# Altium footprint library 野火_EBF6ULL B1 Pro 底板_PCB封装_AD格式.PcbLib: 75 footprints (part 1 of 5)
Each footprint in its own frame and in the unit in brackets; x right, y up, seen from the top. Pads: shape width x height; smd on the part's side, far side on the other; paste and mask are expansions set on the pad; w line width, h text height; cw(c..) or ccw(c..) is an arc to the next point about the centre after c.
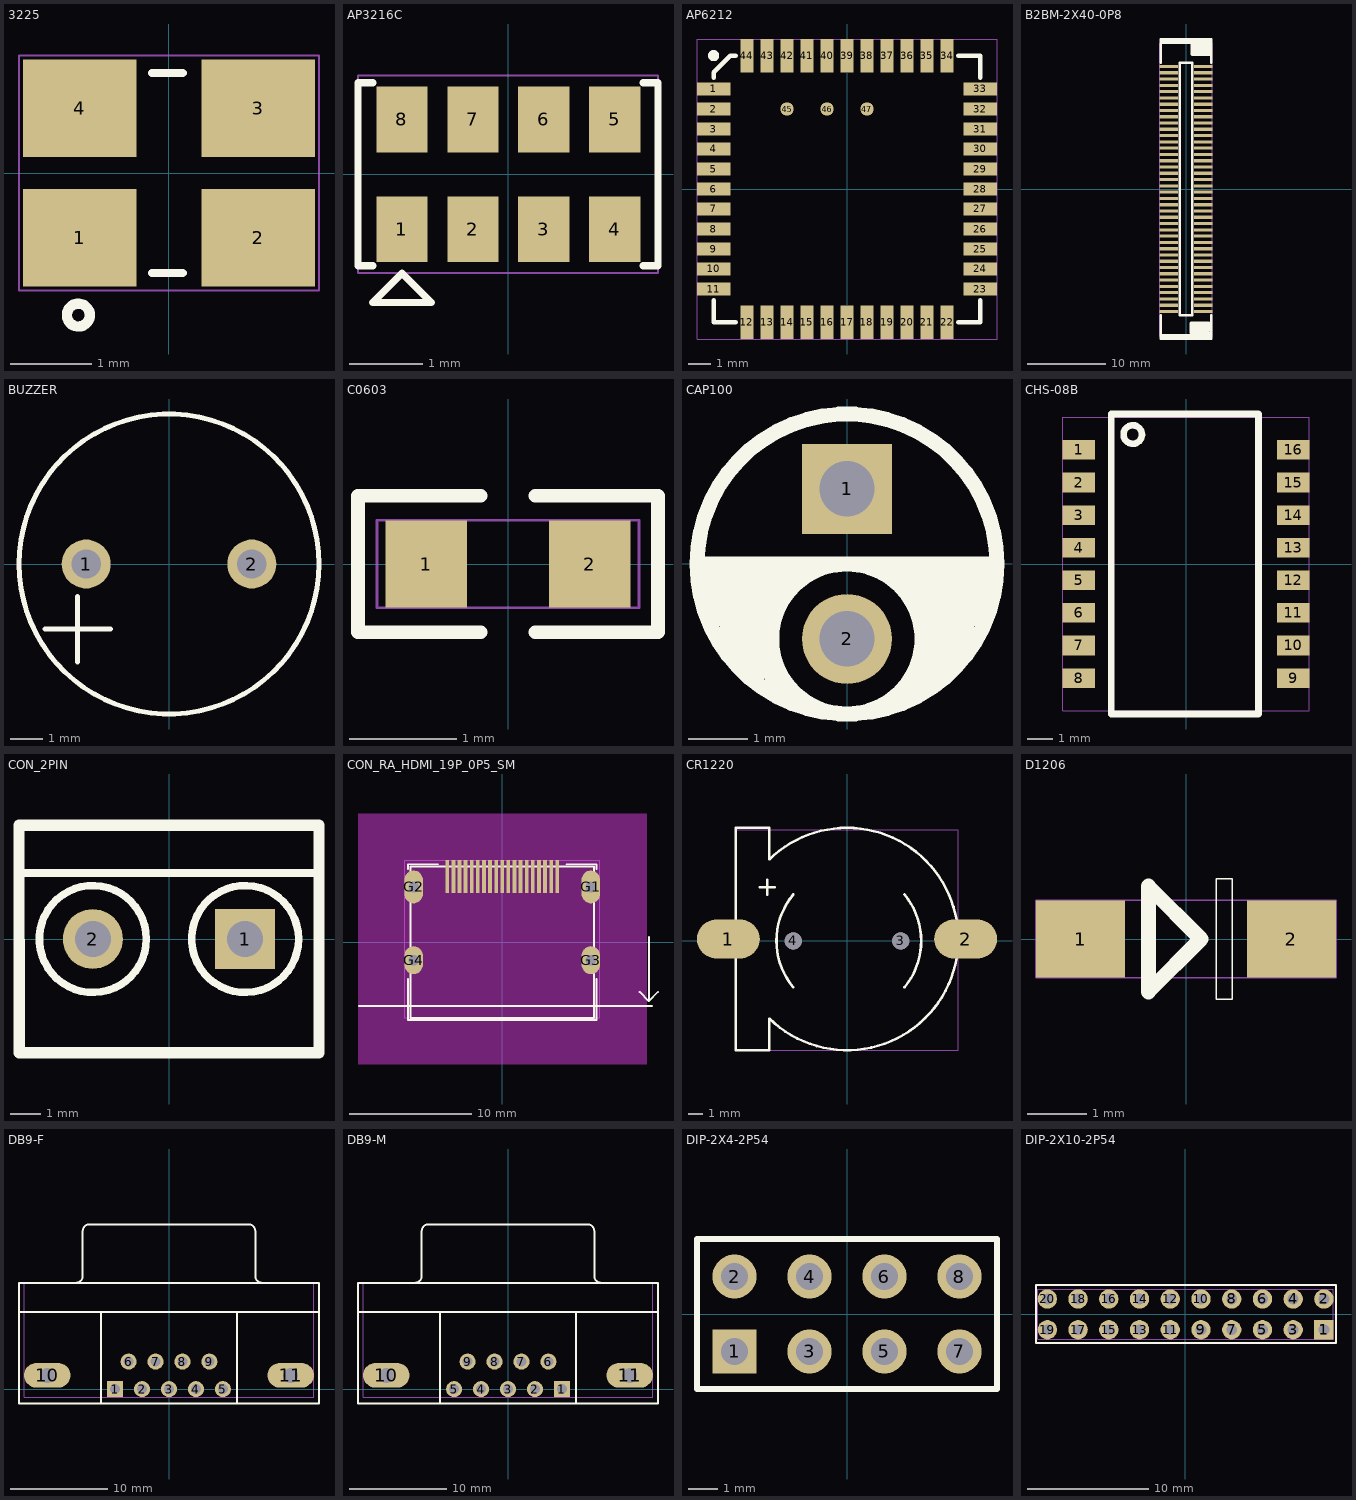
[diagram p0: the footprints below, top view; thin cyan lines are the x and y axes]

## 3225 [mil]
pads (4):
  rect 55.12x47.24 smd mask+1.97: 1(-43.3,-31.5) 2(43.31,-31.5) 3(43.31,31.49) 4(-43.3,31.49)
Top Overlay:
  circle w5: c-44,-69 r5.57
  lines w3.94: -8.3,-48.51 6.7,-48.51 ; -8.3,48.51 6.7,48.51
Top Assembly:
  text "Y2" at -38.93,-25 h50
Mechanical 20:
  lines w1: -72.83,-57.09 -72.83,57.08 72.84,57.08 72.84,-57.09 -72.83,-57.09

## AP3216C [mil]
pads (8):
  rect 27.56x35.43 smd mask+0.98: 1(-57.28,-29.53) 2(-19.09,-29.53) 3(19.09,-29.53) 4(57.28,-29.53) 5(57.28,29.53) 6(19.09,29.53) 7(-19.09,29.53) 8(-57.28,29.53)
Top Overlay:
  lines w3.94: -73.03,-49.21 -80.91,-49.21 -80.91,49.21 -73.03,49.21 ; 72.64,-49.21 80.51,-49.21 80.51,49.21 72.64,49.21 ; -73.03,-68.9 -41.54,-68.9 -57.28,-53.15 -73.03,-68.9
Top Assembly:
  text "U15" at 58.56,25 h50
Mechanical 20:
  lines w1: -80.91,-53.15 80.51,-53.15 80.51,53.15 -80.91,53.15 -80.91,-53.15

## AP6212 [mm]
pads (47):
  rect 1.5x0.6 smd mask+0.05: 1(-6,4.5) 2(-6,3.6) 3(-6,2.7) 4(-6,1.8) 5(-6,0.9) 6(-6,0) 7(-6,-0.9) 8(-6,-1.8) 9(-6,-2.7) 10(-6,-3.6) 11(-6,-4.5) 23(6,-4.5) 24(6,-3.6) 25(6,-2.7) 26(6,-1.8) 27(6,-0.9) 28(6,0) 29(6,0.9) 30(6,1.8) 31(6,2.7) 32(6,3.6) 33(6,4.5)
  rect 0.6x1.5 smd mask+0.05: 12(-4.5,-6) 13(-3.6,-6) 14(-2.7,-6) 15(-1.8,-6) 16(-0.9,-6) 17(0,-6) 18(0.9,-6) 19(1.8,-6) 20(2.7,-6) 21(3.6,-6) 22(4.5,-6) 34(4.5,6) 35(3.6,6) 36(2.7,6) 37(1.8,6) 38(0.9,6) 39(0,6) 40(-0.9,6) 41(-1.8,6) 42(-2.7,6) 43(-3.6,6) 44(-4.5,6)
  round 0.6 smd mask+0.05: 45(-2.7,3.6) 46(-0.9,3.6) 47(0.9,3.6)
Top Overlay:
  circle w0.25: c-6,6 r0.125
  lines w0.2: -6,-5 -6,-6 -5,-6 ; -6,5 -6,5.25 -5.25,6 -5,6 ; 5,-6 6,-6 6,-5 ; 5,6 6,6 6,5
Top Assembly:
  text "U5" at 1.022,0.635 h1.27
Mechanical 20:
  lines w0.025: -6.75,-6.75 6.75,-6.75 6.75,6.75 -6.75,6.75 -6.75,-6.75

## B2BM-2X40-0P8 [mm]
pads (80):
  rect 2.3x0.4 smd mask+0.05: 1(2.2,15.6) 2(-2.2,15.6) 3(2.2,14.8) 4(-2.2,14.8) 5(2.2,14) 6(-2.2,14) 7(2.2,13.2) 8(-2.2,13.2) 9(2.2,12.4) 10(-2.2,12.4) 11(2.2,11.6) 12(-2.2,11.6) 13(2.2,10.8) 14(-2.2,10.8) 15(2.2,10) 16(-2.2,10) 17(2.2,9.2) 18(-2.2,9.2) 19(2.2,8.4) 20(-2.2,8.4) 21(2.2,7.6) 22(-2.2,7.6) 23(2.2,6.8) 24(-2.2,6.8) 25(2.2,6) 26(-2.2,6) 27(2.2,5.2) 28(-2.2,5.2) 29(2.2,4.4) 30(-2.2,4.4) 31(2.2,3.6) 32(-2.2,3.6) 33(2.2,2.8) 34(-2.2,2.8) 35(2.2,2) 36(-2.2,2) 37(2.2,1.2) 38(-2.2,1.2) 39(2.2,0.4) 40(-2.2,0.4) 41(2.2,-0.4) 42(-2.2,-0.4) 43(2.2,-1.2) 44(-2.2,-1.2) 45(2.2,-2) 46(-2.2,-2) 47(2.2,-2.8) 48(-2.2,-2.8) 49(2.2,-3.6) 50(-2.2,-3.6) 51(2.2,-4.4) 52(-2.2,-4.4) 53(2.2,-5.2) 54(-2.2,-5.2) 55(2.2,-6) 56(-2.2,-6) 57(2.2,-6.8) 58(-2.2,-6.8) 59(2.2,-7.6) 60(-2.2,-7.6) 61(2.2,-8.4) 62(-2.2,-8.4) 63(2.2,-9.2) 64(-2.2,-9.2) 65(2.2,-10) 66(-2.2,-10) 67(2.2,-10.8) 68(-2.2,-10.8) 69(2.2,-11.6) 70(-2.2,-11.6) 71(2.2,-12.4) 72(-2.2,-12.4) 73(2.2,-13.2) 74(-2.2,-13.2) 75(2.2,-14) 76(-2.2,-14) 77(2.2,-14.8) 78(-2.2,-14.8) 79(2.2,-15.6) 80(-2.2,-15.6)
Top Overlay:
  lines w0.305: -3.2,-16.1 -3.2,-19.1 3.2,-19.1 3.2,-16.1 ; -3.2,16.1 -3.2,19.1 3.2,19.1 3.2,16.1 ; -0.8,-16.1 -0.8,16.1 0.8,16.1 0.8,-16.1 -0.8,-16.1
  lines w0.5: -3,-18.7 3,-18.7 ; -3,18.7 3,18.7 ; 0.7,-17.9 2.9,-17.9 ; 0.7,-17.5 2.9,-17.5 ; 0.8,17.6 3,17.6 ; 0.8,18 3,18 ; 2.9,-18.3 0.7,-18.3 0.7,-17.1 2.9,-17.1 ; 3,17.2 0.8,17.2 0.8,18.4 3,18.4
Top Assembly:
  text "CN2" at -1.654,-0.635 h1.27
Mechanical 20:
  lines w0.025: -3.35,-18.75 3.35,-18.75 3.35,18.55 -3.35,18.55 -3.35,-18.75

## BUZZER [mil]
pads (2):
  round 59.06 hole 35.43 mask+2: 1(-100,0) 2(100,0)
Top Overlay:
  circle w6: c0,0 r181.1
  lines w6: -149.61,-78.74 -70.87,-78.74 ; -110.24,-118.11 -110.24,-39.37
Top Assembly:
  text "PZ1" at 50.47,25 h50
Mechanical 20:
  circle w1: c0,0 r181.1

## C0603 [mil]
pads (2):
  rect 30x32 smd mask+2.5: 1(-30,0) 2(30,0)
Top Overlay:
  lines w5: -10,-25 -55,-25 -55,25 -10,25 ; 10,-25 55,-25 55,25 10,25
Top Assembly:
  text "C99" at -62.61,-25 h50
Mechanical 20:
  lines w1: -48,-16 -48,16 48,16 48,-16 -48,-16

## CAP100 [mil]
pads (2):
  rect 60x60 hole 37 mask+2: 1(0,50)
  round 60 hole 37 mask+2: 2(0,-50)
Top Overlay:
  circle w10: c0,0 r100
  lines w10: -100,0 100,0 ; -90,-40 -90,0 ; -80,-60 -80,-5 ; -70,-70 -70,-5 ; -60,-75 -60,-5 ; -50,-85 -50,0 ; -45,-85 -45,-80 ; -40,-20 -40,0 ; -30,-10 -30,0 ; 35,-10 35,-5 ; 40,-20 40,-5 ; 45,-85 45,-80 ; 50,-85 50,-5 ; 60,-80 60,-5 ; 70,-70 70,-5 ; 80,-60 80,-5 ; 90,-40 90,-5 ; 0,-100 cw(c-0.26,-50) 0,0 cw(c0,-50) 0,-100
Top Assembly:
  text "C97" at -63.8,-25 h50
Mechanical 20:
  circle w1: c0,0 r100

## CHS-08B [mil]
pads (16):
  rect 50x30 smd mask+2.5: 1(-164.37,175) 2(-164.37,125) 3(-164.37,75) 4(-164.37,25) 5(-164.37,-25) 6(-164.37,-75) 7(-164.37,-125) 8(-164.37,-175) 9(164.37,-175) 10(164.37,-125) 11(164.37,-75) 12(164.37,-25) 13(164.37,25) 14(164.37,75) 15(164.37,125) 16(164.37,175)
Top Overlay:
  circle w10: c-81.69,198.62 r14.19
  lines w10: -114.37,-230.12 -114.37,230.12 111.22,230.12 111.22,-230.12 -114.37,-230.12
Top Assembly:
  text "SW5" at -67.73,-25 h50
Mechanical 20:
  lines w1: -189.37,-225 -189.37,225 189.37,225 189.37,-225 -189.37,-225

## CON_2PIN [mm]
pads (2):
  rect 2x2 hole 1.2 mask+0.051: 1(2.54,0)
  round 2 hole 1.2 mask+0.051: 2(-2.54,0)
Top Overlay:
  circle w0.254: c-2.54,0 r1.783
  circle w0.254: c2.54,0 r1.783
  lines w0.254: -5.004,2.2 5.004,2.2
  lines w0.381: -5.004,3.8 -5,-3.8 5.004,-3.8 5.004,3.8 -5.004,3.8
Top Assembly:
  text "J6" at -0.859,-0.635 h1.27
Mechanical 20:
  lines w0.025: -5.004,-3.8 5.004,-3.8 5.004,3.8 -5.004,3.8 -5.004,-3.8

## CON_RA_HDMI_19P_0P5_SM [mil]
height 249
pads (23):
  rect 12x106 smd mask+2: 1(177.17,211.61) 2(157.48,211.61) 3(137.8,211.61) 4(118.11,211.61) 5(98.43,211.61) 6(78.74,211.61) 7(59.06,211.61) 8(39.37,211.61) 9(19.69,211.61) 10(0,211.61) 11(-19.69,211.61) 12(-39.37,211.61) 13(-59.06,211.61) 14(-78.74,211.61) 15(-98.43,211.61) 16(-118.11,211.61) 17(-137.8,211.61) 18(-157.48,211.61) 19(-177.17,211.61)
  oval 59x106 hole 35 mask+2: G1(285.43,178.15) G2(-285.43,178.15)
  oval 59x90 hole 35 mask+2: G3(285.43,-58.07) G4(-285.43,-58.07)
Top Layer keep-out:
  region: -464.93,-394.09 -464.93,414.61 464.93,414.61 464.93,-394.09
Top Overlay:
  lines w6: -462.6,-205.71 285.43,-205.71 482.28,-205.71 ; -303.26,-118.11 -303.26,-251.09 303.26,-251.09 303.26,-118.11 ; -303.26,236.22 -303.26,251.09 -206.69,251.09 ; 206.69,251.09 303.26,251.09 303.26,236.22 ; 442.91,-160.43 472.44,-189.96 ; 472.44,16.73 472.44,-189.96 ; 501.97,-160.43 472.44,-189.96 ; -296.26,-244.09 -296.26,244.09 296.26,244.09 296.26,-244.09 -296.26,-244.09
Top Assembly:
  text "J1001" at -87.13,-25 h50
Mechanical 20:
  lines w1: -314.93,-244.09 -314.93,264.61 314.93,264.61 314.93,-244.09 -314.93,-244.09

## CR1220 [mil]
pads (4):
  oval 169.29x106.3 smd mask+1.97: 1(-320,5) 2(320,5)
  round 46 hole 46 unplated mask+2: 3(145,0) 4(-145,0)
Top Overlay:
  lines w7: -235,145 -195,145 ; -215,125 -215,165 ; -209.62,-209.61 -210,-295 -300,-295 -300,5 -300,305 -210,305 -209.62,219.61 ; -209.52,-209.7 ccw(c0,5) 298.19,-27.92 ; -209.52,219.71 cw(c0,5.01) 0,305 cw(c0,5) 298.19,37.92 ; -145.23,-124.72 cw(c5,0) -145.01,124.99 ; 155.01,-124.99 ccw(c5,0) 155.01,124.98
Top Assembly:
  text "CN3" at -65.11,-25 h50
Mechanical 20:
  lines w1: -300,-295 -300,300 300,300 300,-295 -300,-295

## D1206 [mil]
pads (2):
  rect 59.06x51.18 smd mask+2: 1(-70,0) 2(70,0)
Top Overlay:
  lines w1: 20,-40 20,40 30.75,40 30.75,-40 20,-40
  lines w10: -25,-35 10,0 -25,35 -25,-35
Top Assembly:
  text "D10" at -57.25,-25 h50
Mechanical 20:
  lines w1: -99.53,-25.59 99.53,-25.59 99.53,25.59 -99.53,25.59 -99.53,-25.59

## DB9-F [mil]
pads (11):
  rect 65x65 hole 40 mask+2: 1(-218.11,0)
  round 65 hole 40 mask+2: 2(-109.06,0) 3(0,0) 4(109.06,0) 5(218.11,0) 6(-163.58,111.81) 7(-54.53,111.81) 8(54.53,111.81) 9(163.58,111.81)
  oval 188x100 hole 60 mask+2: 10(-491.93,55.91) 11(491.93,55.9)
Top Overlay:
  lines w7.87: -606.3,311.81 606.3,311.81 ; -376.38,430.12 ccw(c-376.38,457.48) -349.02,457.48 -348.82,638.78 cw(c-321.46,638.78) -321.46,666.14 321.46,666.14 cw(c321.46,638.78) 348.82,638.78 349.02,457.48 ccw(c376.38,457.48) 376.38,430.12 ; -275.59,-58.27 -275.59,311.81 ; 275.59,-58.27 275.59,311.81 ; -606.3,-58.27 606.3,-58.27 606.3,429.92 -606.3,429.92 -606.3,-58.27
Top Assembly:
  text "CON1" at -79.27,-25 h50
Mechanical 20:
  lines w1: -585.63,-32.5 585.63,-32.5 585.63,429.92 -585.63,429.92 -585.63,-32.5

## DB9-M [mil]
pads (11):
  rect 65x65 hole 40 mask+2: 1(218.11,0)
  round 65 hole 40 mask+2: 2(109.06,0) 3(0,0) 4(-109.06,0) 5(-218.11,0) 6(163.58,111.81) 7(54.53,111.81) 8(-54.53,111.81) 9(-163.58,111.81)
  oval 188x100 hole 60 mask+2: 10(-491.93,55.91) 11(491.93,55.9)
Top Overlay:
  lines w7.87: -606.3,311.81 606.3,311.81 ; -376.38,430.12 ccw(c-376.38,457.48) -349.02,457.48 -348.82,638.78 cw(c-321.46,638.78) -321.46,666.14 321.46,666.14 cw(c321.46,638.78) 348.82,638.78 349.02,457.48 ccw(c376.38,457.48) 376.38,430.12 ; -275.59,-58.27 -275.59,311.81 ; 275.59,-58.27 275.59,311.81 ; -606.3,-58.27 606.3,-58.27 606.3,429.92 -606.3,429.92 -606.3,-58.27
Top Assembly:
  text "CON2" at -89.99,-25 h50
Mechanical 20:
  lines w1: -585.63,-32.5 585.63,-32.5 585.63,429.92 -585.63,429.92 -585.63,-32.5

## DIP-2X4-2P54 [mil]
pads (8):
  rect 59.06x59.06 hole 35.43 mask+2: 1(-150,-50)
  round 59.06 hole 35.43 mask+2: 2(-150,50) 3(-50,-50) 4(-50,50) 5(50,-50) 6(50,50) 7(150,-50) 8(150,50)
Top Overlay:
  lines w8.66: -189.37,100 -200,100 ; -200,100 200,100 200,-100 -200,-100 -200,100
Top Assembly:
  text "J8" at 35,25 h50
Mechanical 20:
  lines w1: -200,-100 -200,100 200,100 200,-100 -200,-100

## DIP-2X10-2P54 [mil]
pads (20):
  rect 62.99x62.99 hole 35.43 mask+2: 1(451.57,-50)
  round 62.99 hole 35.43 mask+2: 2(451.57,50) 3(351.57,-50) 4(351.57,50) 5(251.57,-50) 6(251.57,50) 7(151.57,-50) 8(151.57,50) 9(51.57,-50) 10(51.57,50) 11(-48.43,-50) 12(-48.43,50) 13(-148.43,-50) 14(-148.43,50) 15(-248.43,-50) 16(-248.43,50) 17(-348.43,-50) 18(-348.43,50) 19(-448.43,-50) 20(-448.43,50)
Top Overlay:
  lines w5.91: -485.43,-93.31 -485.43,95.67 490.94,95.67 490.94,-93.31 -485.43,-93.31
Top Assembly:
  text "J21" at 46.54,25 h50
Mechanical 20:
  lines w1: -479.92,-81.5 -479.92,81.49 481.5,81.49 481.5,-81.5 -479.92,-81.5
